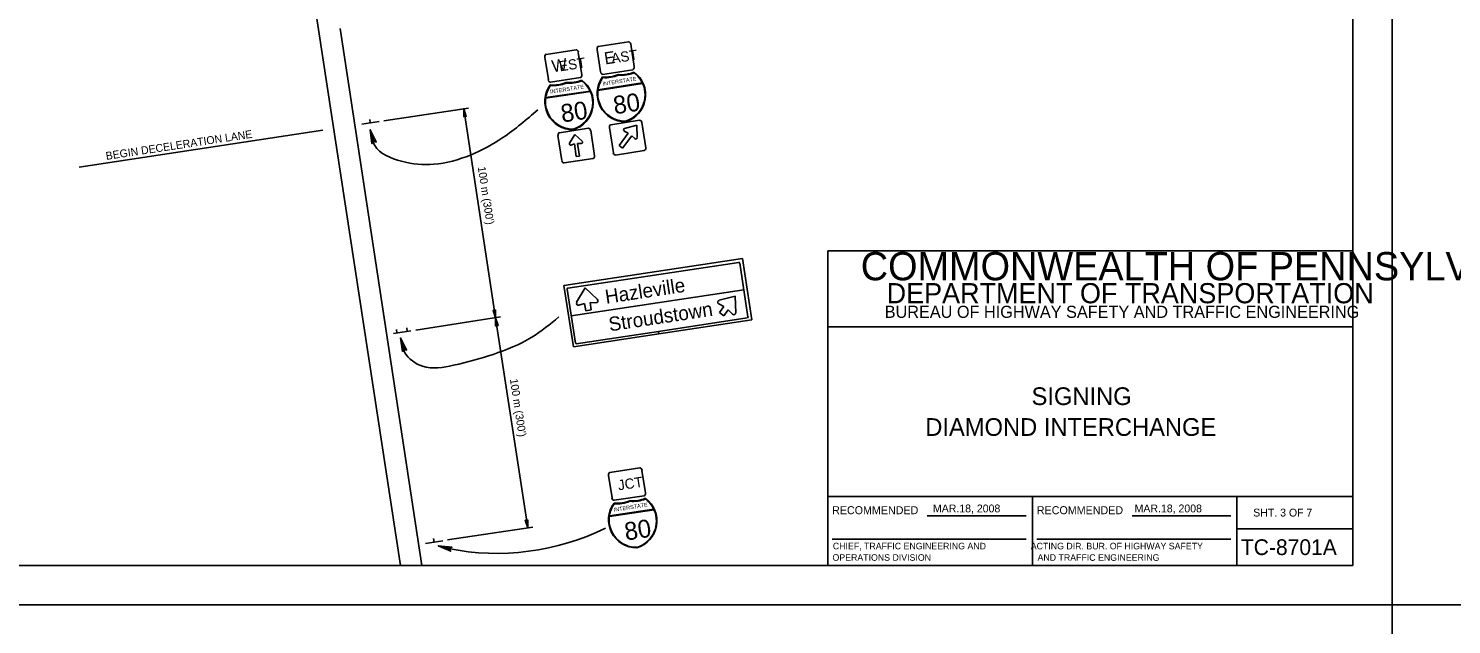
# Model space of a CAD drawing. Extents: x 640994 to 644422, y 298458 to 299646.
# Drawn here: x 642998 to 643540, y 299044 to 299271 of the extents above; entities that cross this region are included whole.
import ezdxf

# ---------------------------------------------------------------- set-up
doc = ezdxf.new("R2010")
doc.units = 0
for name, color, linetype in [('1', 7, 'Continuous'), ('2', 7, 'Continuous'), ('PLT-BNDY', 7, 'Continuous'), ('XCS-GRID-MIN', 7, 'Continuous')]:
    doc.layers.add(name, color=color, linetype=linetype)

msp = doc.modelspace()

# ---------------------------------------------------------------- linework, layer by layer
at = {"layer": '1'}
for p, q in [((643502.31, 299066.63), (643502.31, 299630.63)), ((643302.31, 299066.63), (643302.31, 299186.63)), ((643302.31, 299186.63), (643502.31, 299186.63)), ((643502.31, 299157.63), (643302.31, 299157.63)), ((643302.31, 299093), (643502.31, 299093)), ((643380.31, 299093), (643380.31, 299066.63)), ((643458.19, 299066.63), (643458.19, 299093)), ((643340.24, 299085.57), (643377.87, 299085.57)), ((643418.24, 299085.57), (643455.87, 299085.57)), ((643458.19, 299080.63), (643502.31, 299080.63)), ((643303.99, 299076.68), (643377.87, 299076.68)), ((643381.99, 299076.68), (643455.87, 299076.68)), ((643502.31, 299066.63), (642716.31, 299066.63)), ((642716.31, 299066.63), (643302.31, 299066.63))]:
    msp.add_line(p, q, dxfattribs=at)
at = {"layer": '2'}
for p, q in [((643102.81, 299307.63), (643139.56, 299066.63)), ((643116.56, 299271.38), (643147.69, 299066.63)), ((643195.06, 299261.5), (643206.56, 299263.25)), ((643207.31, 299262.25), (643208.69, 299253.75)), ((643215.81, 299254.88), (643214.56, 299263.38)), ((643214.94, 299264.5), (643226.44, 299266.25)), ((643227.31, 299265.38), (643228.56, 299256.88)), ((643195.94, 299251.88), (643194.56, 299260.38)), ((643201.56, 299257.13), (643201.56, 299257.13)), ((643221.56, 299260.13), (643221.56, 299260.13)), ((643208.19, 299252.63), (643196.69, 299250.88)), ((643208.69, 299251.38), (643208.69, 299251.38)), ((643228.06, 299255.63), (643216.56, 299253.88)), ((643216.69, 299252.63), (643216.69, 299252.63)), ((643222.56, 299253.63), (643222.56, 299253.63)), ((643228.56, 299254.5), (643228.56, 299254.5)), ((643194.81, 299244.75), (643211.94, 299247.38)), ((643211.81, 299247.5), (643194.94, 299245)), ((643196.81, 299249.63), (643196.81, 299249.63)), ((643202.69, 299250.5), (643202.69, 299250.5)), ((643231.69, 299250.63), (643214.81, 299248)), ((643214.81, 299247.75), (643231.81, 299250.38)), ((643133.31, 299236.13), (643165.56, 299241)), ((643175.81, 299161), (643163.69, 299240.75)), ((643204.06, 299241.75), (643204.06, 299241.75)), ((643223.94, 299244.75), (643223.94, 299244.75)), ((643131.44, 299235.88), (643124.81, 299234.88)), ((643128.06, 299235.38), (643127.94, 299236.63)), ((643219.69, 299234.63), (643230.69, 299236.38)), ((643231.56, 299235.5), (643233.06, 299225.88)), ((643017.19, 299218.5), (643110.06, 299232.63)), ((643122.19, 299234.38), (643122.19, 299234.38)), ((643201.06, 299221), (643199.56, 299230.63)), ((643200.19, 299231.63), (643211.19, 299233.38)), ((643203.94, 299227.63), (643205.94, 299231)), ((643205.94, 299231), (643203.94, 299227.63)), ((643205.94, 299231), (643208.81, 299228.38)), ((643208.81, 299228.38), (643205.94, 299231)), ((643212.06, 299232.5), (643213.44, 299222.88)), ((643220.69, 299224), (643219.19, 299233.63)), ((643226.31, 299231.5), (643222.94, 299226.75)), ((643224.19, 299225.75), (643227.69, 299230.5)), ((643224.81, 299232.25), (643226.31, 299231.5)), ((643229.56, 299234.5), (643224.94, 299233.25)), ((643226.06, 299229.75), (643226.06, 299229.75)), ((643227.69, 299230.5), (643228.81, 299229.38)), ((643229.69, 299229.75), (643229.56, 299234.5)), ((643205.81, 299227.38), (643204.44, 299226.88)), ((643204.44, 299226.88), (643205.81, 299227.38)), ((643206.56, 299222.5), (643205.81, 299227.38)), ((643205.81, 299227.38), (643206.56, 299222.5)), ((643208.44, 299227.5), (643207.06, 299227.5)), ((643207.06, 299227.5), (643207.81, 299222.75)), ((643207.81, 299222.75), (643207.06, 299227.5)), ((643207.06, 299227.5), (643208.44, 299227.5)), ((643232.44, 299224.88), (643221.44, 299223.13)), ((643222.94, 299226.75), (643224.19, 299225.75)), ((643212.94, 299221.75), (643201.94, 299220.13)), ((643207.81, 299222.75), (643206.56, 299222.5)), ((643206.56, 299222.5), (643207.81, 299222.75)), ((643269.81, 299183.63), (643201.81, 299173.38)), ((643203.31, 299172.38), (643268.44, 299182.13)), ((643268.81, 299181.88), (643271.94, 299161.38)), ((643273.44, 299160.25), (643269.81, 299183.63)), ((643201.81, 299173.38), (643205.44, 299150)), ((643206.19, 299151.38), (643203.06, 299172)), ((643204.56, 299161.88), (643270.31, 299171.75)), ((643209.94, 299172.5), (643206.69, 299167)), ((643209.94, 299172.5), (643206.69, 299167)), ((643214.56, 299168.13), (643209.94, 299172.5)), ((643214.56, 299168.13), (643209.94, 299172.5)), ((643207.56, 299165.88), (643209.69, 299166.5)), ((643207.56, 299165.88), (643209.69, 299166.5)), ((643209.69, 299166.5), (643210.19, 299163.75)), ((643209.69, 299166.5), (643210.19, 299163.75)), ((643212.19, 299164.13), (643211.81, 299166.88)), ((643211.81, 299166.88), (643214.06, 299166.75)), ((643212.19, 299164.13), (643211.81, 299166.88)), ((643211.81, 299166.88), (643214.06, 299166.75)), ((643237.56, 299166.75), (643237.56, 299166.75)), ((643262.81, 299165.38), (643260.81, 299166.38)), ((643262.81, 299165.38), (643260.81, 299166.38)), ((643260.94, 299167.75), (643267.06, 299169.38)), ((643260.94, 299167.75), (643267.06, 299169.38)), ((643267.06, 299169.38), (643260.94, 299167.75)), ((643260.94, 299167.75), (643267.06, 299169.38)), ((643260.94, 299167.75), (643267.06, 299169.38)), ((643267.06, 299169.38), (643260.94, 299167.75)), ((643261.06, 299163.13), (643262.81, 299165.38)), ((643261.06, 299163.13), (643262.81, 299165.38)), ((643267.06, 299169.38), (643267.31, 299163)), ((643267.06, 299169.38), (643267.31, 299163)), ((643145.44, 299156.38), (643177.69, 299161.38)), ((643188.06, 299081), (643175.81, 299161)), ((643210.19, 299163.75), (643212.19, 299164.13)), ((643210.19, 299163.75), (643212.19, 299164.13)), ((643271.69, 299161), (643237.87, 299155.87)), ((643238.02, 299154.91), (643273.44, 299160.25)), ((643262.81, 299161.88), (643261.06, 299163.13)), ((643262.81, 299161.88), (643261.06, 299163.13)), ((643264.44, 299164.13), (643262.81, 299161.88)), ((643264.44, 299164.13), (643262.81, 299161.88)), ((643266.06, 299162.5), (643264.44, 299164.13)), ((643266.06, 299162.5), (643264.44, 299164.13)), ((643266.06, 299162.5), (643266.06, 299162.5)), ((643134.31, 299154.75), (643134.31, 299154.75)), ((643143.56, 299156.13), (643136.94, 299155.13)), ((643138.19, 299155.38), (643138.06, 299156.63)), ((643142.19, 299155.88), (643142.06, 299157.25)), ((643205.44, 299150), (643238.02, 299154.91)), ((643237.87, 299155.87), (643206.56, 299151.13)), ((643237.87, 299155.87), (643238.02, 299154.91)), ((643238.02, 299154.91), (643237.87, 299155.87)), ((643220.19, 299092.5), (643218.81, 299101)), ((643219.31, 299102.13), (643230.81, 299103.88)), ((643231.56, 299102.88), (643232.94, 299094.38)), ((643225.81, 299097.63), (643225.81, 299097.63)), ((643232.44, 299093.25), (643220.94, 299091.5)), ((643221.06, 299090.25), (643221.06, 299090.25)), ((643226.94, 299091.13), (643226.94, 299091.13)), ((643232.94, 299092), (643232.94, 299092)), ((643236.06, 299088.13), (643219.19, 299085.63)), ((643219.19, 299085.38), (643236.19, 299087.88)), ((643157.56, 299076.38), (643189.94, 299081.25)), ((643146.44, 299075), (643146.44, 299075)), ((643146.44, 299074.63), (643146.44, 299074.63)), ((643155.69, 299076), (643149.06, 299075)), ((643152.44, 299075.5), (643152.19, 299076.88))]:
    msp.add_line(p, q, dxfattribs=at)
for points in [[(643163.76, 299237.88), (643163.95, 299238.01), (643163.69, 299240.75), (643163.76, 299237.88), (643163.66, 299237.71), (643163.69, 299240.75), (643164.23, 299238.06), (643164.45, 299237.99), (643163.69, 299240.75), (643164.61, 299237.86), (643164.45, 299237.99)], [(643128.81, 299227.88), (643129.06, 299228.13), (643128.06, 299232.75), (643128.81, 299227.88), (643128.69, 299227.5), (643128.06, 299232.75), (643129.56, 299228.25), (643129.94, 299228.25), (643128.06, 299232.75), (643130.31, 299228), (643129.94, 299228.25)], [(643175.74, 299163.88), (643175.55, 299163.74), (643175.81, 299161), (643175.74, 299163.88), (643175.84, 299164.04), (643175.81, 299161), (643175.27, 299163.7), (643175.05, 299163.76), (643175.81, 299161), (643174.89, 299163.9), (643175.05, 299163.76)], [(643175.89, 299158.13), (643176.08, 299158.26), (643175.81, 299161), (643175.89, 299158.13), (643175.79, 299157.96), (643175.81, 299161), (643176.36, 299158.31), (643176.58, 299158.24), (643175.81, 299161), (643176.74, 299158.11), (643176.58, 299158.24)], [(643140.44, 299148.5), (643140.81, 299148.75), (643139.56, 299153.38), (643140.44, 299148.5), (643140.31, 299148.25), (643139.56, 299153.38), (643141.19, 299149), (643141.56, 299148.88), (643139.56, 299153.38), (643141.94, 299148.75), (643141.56, 299148.88)], [(643187.98, 299083.88), (643187.8, 299083.74), (643188.06, 299081), (643187.98, 299083.88), (643188.09, 299084.04), (643188.06, 299081), (643187.51, 299083.69), (643187.3, 299083.76), (643188.06, 299081), (643187.14, 299083.89), (643187.3, 299083.76)], [(643158.51, 299072.37), (643158.39, 299072.74), (643153.96, 299074.16), (643158.51, 299072.37), (643158.73, 299072.06), (643153.96, 299074.16), (643158.54, 299073.16), (643158.77, 299073.49), (643153.96, 299074.16), (643159.15, 299073.61), (643158.77, 299073.49)]]:
    msp.add_lwpolyline(points, dxfattribs=at)
for centre, radius, start, end in [((643203.86, 299263.04), 12.33, 264.4038, 292.9038), ((643203.86, 299263.04), 12.56, 264.6648, 292.3133), ((643202.3, 299243.04), 10.73, 286.7839, 53.6538), ((643202.3, 299243.04), 10.51, 25.4466, 52.9614), ((643225.23, 299246.52), 10.73, 143.6538, 270.5237), ((643225.23, 299246.52), 10.51, 144.3462, 171.8611), ((643217.79, 299265.16), 12.33, 264.4038, 292.9038), ((643217.79, 299265.16), 12.56, 264.9943, 292.6428), ((643223.79, 299266.07), 12.33, 264.4038, 292.9038), ((643223.79, 299266.07), 12.56, 264.6648, 292.3133), ((643222.23, 299246.07), 10.73, 286.7839, 53.6538), ((643222.23, 299246.07), 10.51, 25.4466, 52.9614), ((643205.3, 299243.49), 10.73, 143.6538, 270.5237), ((643205.3, 299243.49), 10.51, 144.3462, 171.8611), ((643197.86, 299262.12), 12.33, 264.4038, 292.9038), ((643197.86, 299262.12), 12.56, 264.9943, 292.6428), ((643202.3, 299243.04), 10.51, 286.7839, 24.1669), ((643225.23, 299246.52), 10.51, 173.1407, 270.5237), ((643222.23, 299246.07), 10.51, 286.7839, 24.1669), ((643205.3, 299243.49), 10.51, 173.1407, 270.5237), ((643225.07, 299232.74), 0.5, 103.9183, 245.5492), ((643229.19, 299229.7), 0.5, 225, 1.3737), ((643204.37, 299227.38), 0.46, 148.5129, 289.1785), ((643204.37, 299227.38), 0.46, 148.5129, 289.1785), ((643208.49, 299227.98), 0.46, 266.9014, 50.808), ((643208.49, 299227.98), 0.46, 266.9014, 50.8081), ((643268.53, 299181.93), 0.309, 7.3907, 98.4613), ((643203.39, 299172.11), 0.309, 98.9487, 188.5961), ((643207.4, 299166.56), 0.745, 148.5129, 289.1785), ((643207.4, 299166.56), 0.745, 148.5129, 289.1785), ((643214.08, 299167.54), 0.745, 266.9014, 50.8081), ((643214.08, 299167.54), 0.745, 266.9014, 50.8081), ((643261.15, 299167), 0.745, 103.5129, 244.1785), ((643261.15, 299167), 0.745, 103.5129, 244.1785), ((643266.57, 299162.97), 0.745, 221.9014, 5.8081), ((643266.57, 299162.97), 0.745, 221.9014, 5.8081), ((643271.71, 299161.4), 0.309, 278.3685, 10.1781), ((643206.58, 299151.55), 0.309, 189.1727, 276.4437), ((643229.56, 299084.08), 10.73, 143.6538, 270.5237), ((643229.56, 299084.08), 10.51, 144.3462, 171.8611), ((643222.12, 299102.71), 12.33, 264.4038, 292.9038), ((643222.12, 299102.71), 12.56, 264.9943, 292.6428), ((643228.12, 299103.62), 12.33, 264.4038, 292.9038), ((643228.12, 299103.62), 12.56, 264.6648, 292.3133), ((643226.56, 299083.62), 10.73, 286.7839, 53.6538), ((643226.56, 299083.62), 10.51, 25.4466, 52.9614), ((643229.56, 299084.08), 10.51, 173.1407, 270.5237), ((643226.56, 299083.62), 10.51, 286.7839, 24.1669), ((643176.31, 299165.19), 93.92, 258.636, 296.1278)]:
    msp.add_arc(centre, radius, start, end, dxfattribs=at)
for centre, major_axis, ratio, start_param, end_param in [((643206.7, 299262.21), (-0.16, 1.06), 0.6, 4.712389, 6.283185), ((643215.15, 299263.5), (0.16, -1.06), 0.6, 3.141593, 4.712389), ((643226.63, 299265.25), (-0.16, 1.06), 0.6, 4.712389, 6.283185), ((643195.22, 299260.47), (0.16, -1.06), 0.6, 3.141593, 4.712389), ((643227.92, 299256.74), (-0.16, 1.06), 0.6, 3.141593, 4.712389), ((643196.51, 299251.96), (0.16, -1.06), 0.6, 4.712389, 6.283185), ((643207.99, 299253.71), (-0.16, 1.06), 0.6, 3.141593, 4.712389), ((643216.44, 299255), (0.16, -1.06), 0.6, 4.712389, 6.283185), ((643230.85, 299235.42), (-0.14, 0.921), 0.769266, 4.712389, 6.283185), ((643200.32, 299230.73), (0.14, -0.921), 0.769266, 3.141593, 4.712389), ((643211.3, 299232.4), (-0.14, 0.921), 0.769266, 4.712389, 6.283185), ((643219.86, 299233.75), (0.14, -0.921), 0.769266, 3.141593, 4.712389), ((643232.32, 299225.75), (-0.14, 0.921), 0.769266, 3.141593, 4.712389), ((643201.79, 299221.06), (0.14, -0.921), 0.769266, 4.712389, 6.283185), ((643212.78, 299222.73), (-0.14, 0.921), 0.769266, 3.141593, 4.712389), ((643221.33, 299224.08), (0.14, -0.921), 0.769266, 4.712389, 6.283185), ((643219.48, 299101.05), (0.16, -1.06), 0.6, 3.141593, 4.712389), ((643230.96, 299102.8), (-0.16, 1.06), 0.6, 4.712389, 6.283185), ((643232.25, 299094.3), (-0.16, 1.06), 0.6, 3.141593, 4.712389), ((643220.78, 299092.55), (0.16, -1.06), 0.6, 4.712389, 6.283185)]:
    msp.add_ellipse(centre, major_axis=major_axis, ratio=ratio, start_param=start_param, end_param=end_param, dxfattribs=at)
for points in [[(643191.94, 299240.38), (643178.56, 299229.75), (643166.31, 299223.13), (643152.31, 299219.63), (643139.94, 299220.75), (643129.81, 299226.75), (643128.06, 299232.75)], [(643199.94, 299161.38), (643189.56, 299153.63), (643174.94, 299147.13), (643159.81, 299143), (643147.94, 299142.63), (643141.31, 299147.75), (643139.56, 299153.38)]]:
    msp.add_spline(points, degree=3, dxfattribs=at)
at = {"layer": 'XCS-GRID-MIN'}
for points in [[(642676.31, 299645.63), (643517.31, 299645.63), (643517.31, 299051.63), (642676.31, 299051.63)], [(643517.31, 299645.63), (644358.31, 299645.63), (644358.31, 299051.63), (643517.31, 299051.63)], [(642676.31, 299051.63), (643517.31, 299051.63), (643517.31, 298457.63), (642676.31, 298457.63)]]:
    msp.add_lwpolyline(points, close=True, dxfattribs=at)

# ---------------------------------------------------------------- texts
at = {"layer": '1'}
for s, height, p in [('COMMONWEALTH OF PENNSYLVANIA', 10.7828, (643314.9, 299175.36)), ('DEPARTMENT OF TRANSPORTATION', 7.6837, (643324.76, 299166.61)), ('BUREAU OF HIGHWAY SAFETY AND TRAFFIC ENGINEERING', 4.6253, (643324.04, 299161.04)), ('SIGNING', 6.75, (643379.96, 299127.81)), ('DIAMOND INTERCHANGE', 6.75, (643339.49, 299116.06)), ('RECOMMENDED', 3.048, (643303.99, 299086.2)), ('RECOMMENDED', 3.048, (643381.99, 299086.2)), ('SHT. 3 OF 7', 3, (643464.4, 299085.31)), ('TC-8701A', 6, (643459.68, 299070.63))]:
    msp.add_text(s, height=height, dxfattribs=at).set_placement(p)
at = {"layer": '2'}
for s, height, rotation, p in [('E', 4.63, 8.6525, (643217.56, 299257.63)), ('AST', 3.875, 8.6538, (643220.19, 299258)), ('W', 4.63, 8.6525, (643197.56, 299254.63)), ('EST', 3.875, 8.6538, (643200.31, 299255)), ('INTERSTATE', 1.517, 8.6538, (643216.69, 299249.5)), ('INTERSTATE', 1.517, 8.6538, (643196.69, 299246.5)), ('80', 6.829, 8.6538, (643221.19, 299238.63)), ('80', 6.829, 8.6538, (643201.19, 299235.5)), ('BEGIN DECELERATION LANE', 3, 8.6534, (643027.56, 299221.25)), ("100 m (300')", 3, 278.6536, (643169.01, 299218.53)), ('Hazleville  ', 5.3752, 8.6538, (643217.94, 299166.38)), ('Stroudstown', 5.3752, 8.6538, (643219.31, 299155.88)), ("100 m (300')", 3, 278.6537, (643181.26, 299137.65)), ('JCT', 3.896, 8.6538, (643222.69, 299095.25)), ('INTERSTATE', 1.517, 8.6538, (643220.94, 299087.13)), ('80', 6.829, 8.6538, (643225.44, 299076.13))]:
    msp.add_text(s, height=height, rotation=rotation, dxfattribs=at).set_placement(p)
for p in [(643342.41, 299086.89), (643419.21, 299086.89)]:
    msp.add_text('MAR.18, 2008', height=3, dxfattribs=at).set_placement(p)
at = {"layer": 'PLT-BNDY'}
for s, p in [('CHIEF, TRAFFIC ENGINEERING AND', (643304.28, 299072.81)), ('  ACTING DIR. BUR. OF HIGHWAY SAFETY', (643377.81, 299072.8)), ('  ACTING DIR. BUR. OF HIGHWAY SAFETY', (643377.81, 299072.8)), ('OPERATIONS DIVISION', (643304.14, 299068.44))]:
    msp.add_text(s, height=2.5, dxfattribs=at).set_placement(p)
msp.add_text('AND TRAFFIC ENGINEERING', height=2.5, rotation=360, dxfattribs=at).set_placement((643382.25, 299068.43))
msp.add_text('AND TRAFFIC ENGINEERING', height=2.5, rotation=360, dxfattribs=at).set_placement((643382.25, 299068.43))

doc.saveas('drawing.dxf')
